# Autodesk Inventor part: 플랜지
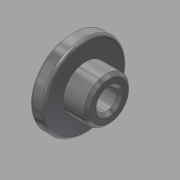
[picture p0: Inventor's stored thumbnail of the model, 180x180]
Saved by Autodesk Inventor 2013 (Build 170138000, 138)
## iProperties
Created: 2018-01
Part Number: 플랜지
Material: 스테인리스강
Document SubType Name: Modeling
Designer: mduedu
Density: 8.08 g/cm^3
Mass: 3.95967 g
Surface Area: 5.35087 cm^2
Volume: 0.490059 cm^3
Author: mduedu
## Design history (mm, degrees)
sketch "스케치1"
  geometry: L1 (0, 0)-(0, 7); L2 (0, 7)-(2.5, 7); L3 (2.5, 7)-(2.5, 3.75); L4 (2.5, 3.75)-(6.5, 3.75); L5 (6.5, 3.75)-(6.5, 0); L6 (6.5, 0)-(0, 0)
  constraints: 12 end point, 4 parallel, 1 perpendicular, 1 vertical
  dimensions: "d0" = 14 diameter of L2 L6; "d2" = 7.5 diameter of L4 L6; "d3" = 2.5 distance of L1.end L2.end; "d4" = 6.5 distance between parallel lines of L5 L1
revolve "회전1" sketch "스케치1" stored, may be unused: angle "d5" = 90 deg
hole "구멍1" diameter "d8" = 3.5; stored, may be unused: countersink angle "d12" = 90 deg, drill point angle "d14" = 118 deg; dims "d9" = 6, "d10" = 4, "d11" = 2, "d13" = 8, "d19" = 10, "d20" = 10
fillet "모깎기1" dims "d15" = 0.5
chamfer "모따기1" distance "d16" = 0.5; stored, may be unused: second distance "d17" = 2, angle "d18" = 45 deg
chamfer "모따기2" distance "d21" = 0.5; stored, may be unused: second distance "d22" = 2, angle "d23" = 45 deg
node "솔리드1"
